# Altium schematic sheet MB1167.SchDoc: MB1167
size A3; DocumentNumber: MB1167; Revision: B.1; SheetNumber: 1; SheetTotal: 17; Project: STM327x6G-EVAL
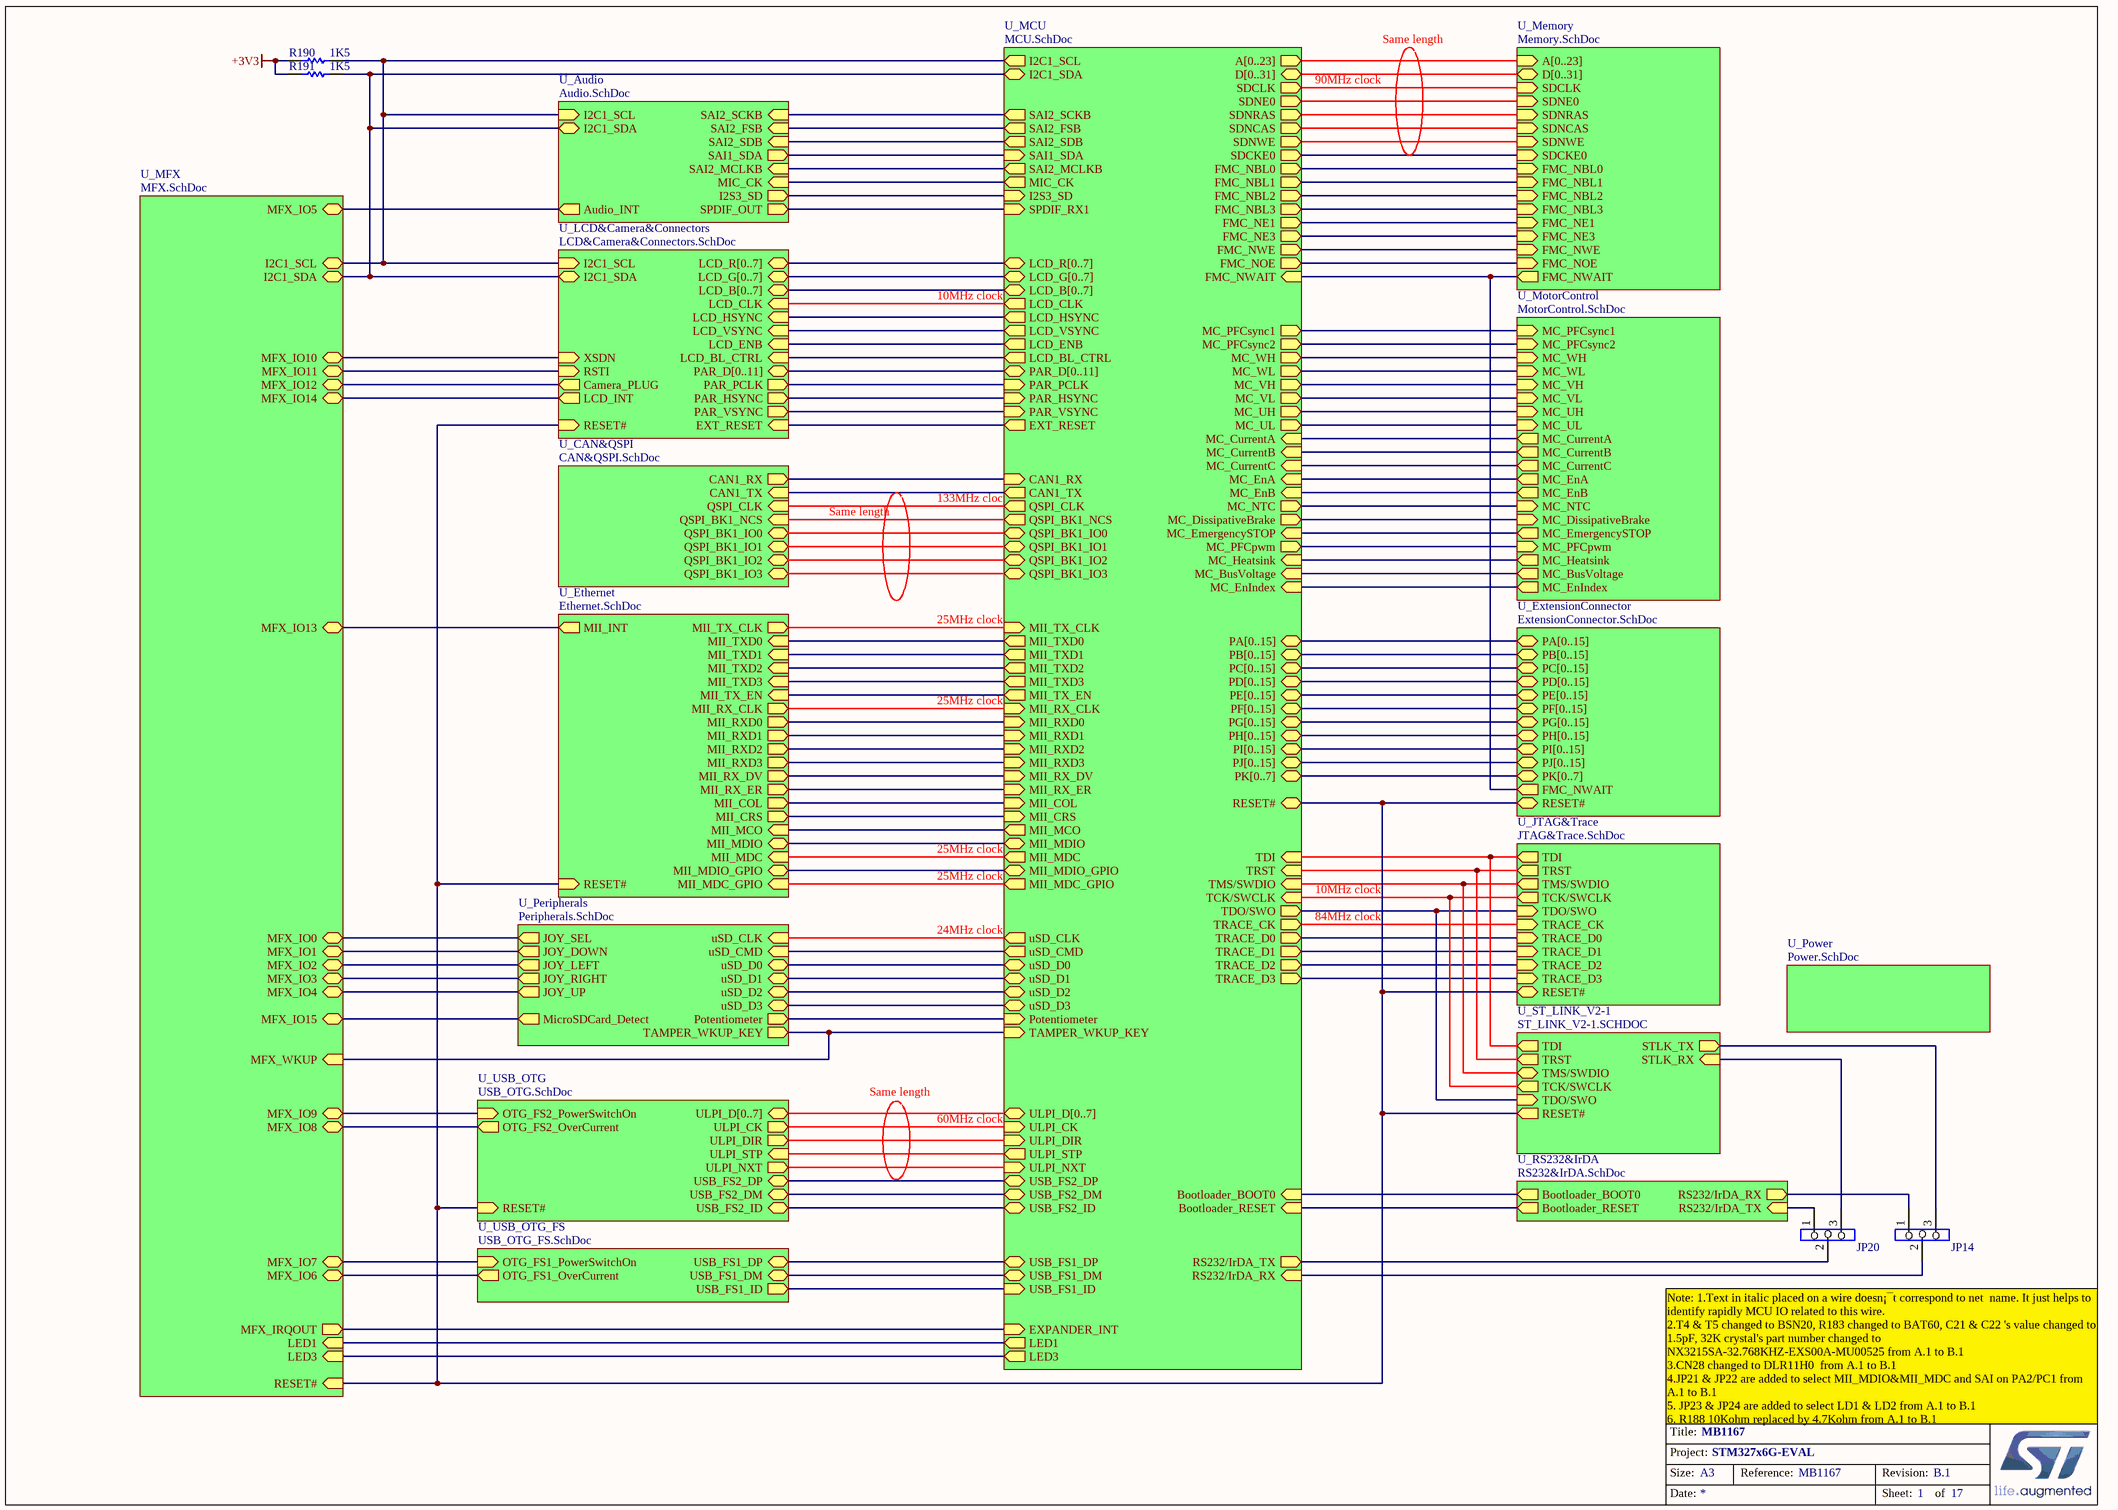
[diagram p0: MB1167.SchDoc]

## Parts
JP14  (no value)  [SIP3]
JP20  (no value)  [SIP3]
R190  1K5  [0603R]
R191  1K5  [0603R]

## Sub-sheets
U_Audio = Audio.SchDoc: SAI2_SCKB (in), SAI2_FSB (in), SAI2_SDB (in), SAI1_SDA (out), Audio_INT (out), I2C1_SDA (bidir), I2C1_SCL (in), SAI2_MCLKB (in), MIC_CK (in), I2S3_SD (out), SPDIF_OUT (out)
U_CAN&QSPI = CAN&QSPI.SchDoc: CAN1_TX (in), CAN1_RX (out), QSPI_BK1_IO0 (bidir), QSPI_BK1_IO3 (bidir), QSPI_BK1_IO2 (bidir), QSPI_BK1_IO1 (bidir), QSPI_CLK (in), QSPI_BK1_NCS (in)
U_Ethernet = Ethernet.SchDoc: MII_TXD0 (in), MII_TX_EN (in), MII_TX_CLK (out), MII_RXD0 (out), MII_RX_ER (out), MII_RX_DV (out), MII_RX_CLK (out), MII_COL (out), MII_CRS (out), MII_MDC (in), MII_MDIO (bidir), RESET# (in), MII_TXD1 (in), MII_TXD2 (in), MII_TXD3 (in), MII_RXD1 (out), MII_RXD2 (out), MII_RXD3 (out), MII_INT (out), MII_MCO (in), MII_MDIO_GPIO (bidir), MII_MDC_GPIO (in)
U_ExtensionConnector = ExtensionConnector.SchDoc: PA[0..15] (bidir), PB[0..15] (bidir), PC[0..15] (bidir), PD[0..15] (bidir), PE[0..15] (bidir), PF[0..15] (bidir), PG[0..15] (bidir), PH[0..15] (bidir), PI[0..15] (bidir), PJ[0..15] (bidir), PK[0..7] (bidir), RESET# (bidir), FMC_NWAIT (out)
U_JTAG&Trace = JTAG&Trace.SchDoc: TDI (out), RESET# (bidir), TRACE_D3 (in), TRACE_D2 (in), TRACE_D1 (in), TRACE_D0 (in), TRACE_CK (in), TRST (out), TMS/SWDIO (out), TCK/SWCLK (out), TDO/SWO (in)
U_LCD&Camera&Connectors = LCD&Camera&Connectors.SchDoc: LCD_R[0..7] (bidir), LCD_HSYNC (in), LCD_VSYNC (in), LCD_CLK (in), LCD_ENB (in), LCD_BL_CTRL (in), I2C1_SDA (bidir), I2C1_SCL (in), LCD_B[0..7] (bidir), LCD_G[0..7] (bidir), RSTI (in), XSDN (in), PAR_HSYNC (out), PAR_PCLK (out), PAR_VSYNC (out), PAR_D[0..11] (bidir), EXT_RESET (in), LCD_INT (out), Camera_PLUG (out), RESET# (in)
U_MCU = MCU.SchDoc: PA[0..15] (bidir), PB[0..15] (bidir), PC[0..15] (bidir), PD[0..15] (bidir), PE[0..15] (bidir), PF[0..15] (bidir), PG[0..15] (bidir), PH[0..15] (bidir), PI[0..15] (bidir), MC_EnA (in), MII_RX_CLK (in), MC_EnB (in), MII_MDIO (bidir), MC_EnIndex (in), ULPI_CK (in), MC_EmergencySTOP (in), MII_RX_DV (in), MC_UL (out), LCD_BL_CTRL (out), MC_PFCsync1 (out), RS232/IrDA_TX (out), RS232/IrDA_RX (in), USB_FS1_ID (in), CAN1_RX (in), USB_FS1_DM (bidir), MC_PFCpwm (out), CAN1_TX (out), USB_FS1_DP (bidir), MC_PFCsync2 (out), TMS/SWDIO (in), TCK/SWCLK (in), TDI (in), MC_VL (out), MC_WL (out), TDO/SWO (out), MIC_CK (out), TRST (in), I2C1_SCL (out), MII_TXD3 (out), MC_DissipativeBrake (out), I2C1_SDA (bidir), USB_FS2_ID (bidir), USB_FS2_DM (bidir), USB_FS2_DP (bidir), ULPI_STP (out), MII_MDC (out), MC_CurrentA (in), MII_TXD2 (out), MC_CurrentB (in), MII_TX_CLK (in), MC_CurrentC (in), MII_RXD0 (in), MC_BusVoltage (in), MII_RXD1 (in), MC_Heatsink (in), MC_UH (out), MC_VH (out), uSD_D0 (bidir), MC_WH (out), uSD_D1 (bidir), uSD_D2 (bidir), EXT_RESET (out), uSD_D3 (bidir), uSD_CLK (out), TAMPER_WKUP_KEY (in), MII_CRS (in), LCD_ENB (out), uSD_CMD (out), FMC_NOE (out), FMC_NWE (out), FMC_NWAIT (in), I2S3_SD (in), FMC_NE1 (out), FMC_NBL3 (out), FMC_NBL2 (out), EXPANDER_INT (in), MII_RX_ER (in), ULPI_DIR (in), LCD_HSYNC (out), LCD_VSYNC (out), LCD_CLK (out), FMC_NBL0 (out), FMC_NBL1 (out), TRACE_CK (out), TRACE_D0 (out), TRACE_D2 (out), TRACE_D1 (out), SAI1_SDA (in), TRACE_D3 (out), SAI2_SDB (out), SAI2_SCKB (out), SAI2_FSB (out), SAI2_MCLKB (out), Potentiometer (in), SDNRAS (out), MII_MDIO_GPIO (bidir), MII_MDC_GPIO (out), SDCLK (out), FMC_NE3 (out), SPDIF_RX1 (in), MII_TX_EN (out), MC_NTC (out), MII_TXD0 (out), MII_TXD1 (out), SDNCAS (out), SDCKE0 (out), SDNE0 (out), MII_COL (in), ULPI_NXT (in), SDNWE (out), MII_RXD2 (in), MII_RXD3 (in), LCD_G[0..7] (bidir), LCD_B[0..7] (bidir), D[0..31] (bidir), A[0..23] (out), ULPI_D[0..7] (bidir), RESET# (bidir), PJ[0..15] (bidir), PK[0..7] (bidir), PAR_VSYNC (in), PAR_D[0..11] (bidir), PAR_PCLK (in), PAR_HSYNC (in), MII_MCO (out), LCD_R[0..7] (bidir), Bootloader_BOOT0 (in), QSPI_CLK (out), QSPI_BK1_NCS (out), QSPI_BK1_IO3 (bidir), QSPI_BK1_IO2 (bidir), QSPI_BK1_IO1 (bidir), QSPI_BK1_IO0 (bidir), Bootloader_RESET (in), LED1 (out), LED3 (out)
U_Memory = Memory.SchDoc: FMC_NE1 (in), FMC_NWE (in), FMC_NOE (in), FMC_NWAIT (out), FMC_NBL0 (in), FMC_NBL1 (in), D[0..31] (bidir), A[0..23] (in), SDNCAS (in), SDNWE (in), SDNRAS (in), SDNE0 (in), SDCKE0 (in), SDCLK (in), FMC_NBL3 (in), FMC_NBL2 (in), FMC_NE3 (in)
U_MFX = MFX.SchDoc: I2C1_SDA (bidir), I2C1_SCL (bidir), MFX_IO5 (bidir), MFX_IO6 (bidir), MFX_IO7 (bidir), MFX_IO8 (bidir), MFX_IO9 (bidir), MFX_IO10 (bidir), MFX_IO11 (bidir), MFX_IO12 (bidir), MFX_IO13 (bidir), MFX_IO14 (bidir), MFX_IO15 (bidir), MFX_IO0 (bidir), MFX_IO1 (bidir), MFX_IO2 (bidir), MFX_IO3 (bidir), MFX_IO4 (bidir), MFX_IRQOUT (out), MFX_WKUP (in), RESET# (in), LED1 (in), LED3 (in)
U_MotorControl = MotorControl.SchDoc: MC_EmergencySTOP (out), MC_CurrentA (out), MC_CurrentB (out), MC_CurrentC (out), MC_PFCsync1 (in), MC_PFCsync2 (in), MC_WL (in), MC_VH (in), MC_VL (in), MC_UH (in), MC_UL (in), MC_WH (in), MC_NTC (in), MC_DissipativeBrake (in), MC_PFCpwm (in), MC_EnA (out), MC_EnB (out), MC_Heatsink (out), MC_BusVoltage (out), MC_EnIndex (out)
U_Peripherals = Peripherals.SchDoc: JOY_SEL (out), JOY_DOWN (out), JOY_LEFT (out), JOY_RIGHT (out), JOY_UP (out), Potentiometer (out), TAMPER_WKUP_KEY (out), uSD_CLK (in), uSD_CMD (in), uSD_D0 (bidir), uSD_D1 (bidir), uSD_D2 (bidir), uSD_D3 (bidir), MicroSDCard_Detect (out)
U_Power = Power.SchDoc: no entries
U_RS232&IrDA = RS232&IrDA.SchDoc: RS232/IrDA_TX (in), RS232/IrDA_RX (out), Bootloader_BOOT0 (out), Bootloader_RESET (out)
U_ST_LINK_V2-1 = ST_LINK_V2-1.SCHDOC: STLK_RX (in), STLK_TX (out), TDI (out), TRST (out), TMS/SWDIO (bidir), TCK/SWCLK (out), TDO/SWO (in), RESET# (out)
U_USB_OTG = USB_OTG.SchDoc: ULPI_D[0..7] (bidir), ULPI_CK (out), ULPI_DIR (out), ULPI_NXT (out), ULPI_STP (in), RESET# (in), USB_FS2_DM (bidir), USB_FS2_DP (bidir), OTG_FS2_PowerSwitchOn (in), OTG_FS2_OverCurrent (out), USB_FS2_ID (bidir)
U_USB_OTG_FS = USB_OTG_FS.SchDoc: OTG_FS1_PowerSwitchOn (in), OTG_FS1_OverCurrent (out), USB_FS1_DM (bidir), USB_FS1_DP (bidir), USB_FS1_ID (out)

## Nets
+3V3: R190.1 R191.1
NetJP14_1: JP14.1 ; sheet U_RS232&IrDA/RS232/IrDA_RX
NetJP14_2: JP14.2 ; sheet U_MCU/RS232/IrDA_RX
NetJP14_3: JP14.3 ; sheet U_ST_LINK_V2-1/STLK_TX
NetJP20_1: JP20.1 ; sheet U_RS232&IrDA/RS232/IrDA_TX
NetJP20_2: JP20.2 ; sheet U_MCU/RS232/IrDA_TX
NetJP20_3: JP20.3 ; sheet U_ST_LINK_V2-1/STLK_RX
NetR190_2: R190.2 ; sheet U_Audio/I2C1_SCL, sheet U_LCD&Camera&Connectors/I2C1_SCL, sheet U_MFX/I2C1_SCL, sheet U_MCU/I2C1_SCL
NetR191_2: R191.2 ; sheet U_Audio/I2C1_SDA, sheet U_LCD&Camera&Connectors/I2C1_SDA, sheet U_MFX/I2C1_SDA, sheet U_MCU/I2C1_SDA
(unnamed): sheet U_Audio/SAI2_SCKB, sheet U_MCU/SAI2_SCKB
(unnamed): sheet U_Audio/SAI2_FSB, sheet U_MCU/SAI2_FSB  [a separate net that carries the same name]
(unnamed): sheet U_Audio/SAI2_SDB, sheet U_MCU/SAI2_SDB  [a separate net that carries the same name]
(unnamed): sheet U_Audio/SAI1_SDA, sheet U_MCU/SAI1_SDA  [a separate net that carries the same name]
(unnamed): sheet U_Audio/Audio_INT, sheet U_MFX/MFX_IO5  [a separate net that carries the same name]
(unnamed): sheet U_Audio/SAI2_MCLKB, sheet U_MCU/SAI2_MCLKB  [a separate net that carries the same name]
(unnamed): sheet U_Audio/MIC_CK, sheet U_MCU/MIC_CK  [a separate net that carries the same name]
(unnamed): sheet U_Audio/I2S3_SD, sheet U_MCU/I2S3_SD  [a separate net that carries the same name]
(unnamed): sheet U_Audio/SPDIF_OUT, sheet U_MCU/SPDIF_RX1  [a separate net that carries the same name]
(unnamed): sheet U_CAN&QSPI/CAN1_TX, sheet U_MCU/CAN1_TX  [a separate net that carries the same name]
(unnamed): sheet U_CAN&QSPI/CAN1_RX, sheet U_MCU/CAN1_RX  [a separate net that carries the same name]
(unnamed): sheet U_CAN&QSPI/QSPI_BK1_IO0, sheet U_MCU/QSPI_BK1_IO0  [a separate net that carries the same name]
(unnamed): sheet U_CAN&QSPI/QSPI_BK1_IO3, sheet U_MCU/QSPI_BK1_IO3  [a separate net that carries the same name]
(unnamed): sheet U_CAN&QSPI/QSPI_BK1_IO2, sheet U_MCU/QSPI_BK1_IO2  [a separate net that carries the same name]
(unnamed): sheet U_CAN&QSPI/QSPI_BK1_IO1, sheet U_MCU/QSPI_BK1_IO1  [a separate net that carries the same name]
(unnamed): sheet U_CAN&QSPI/QSPI_CLK, sheet U_MCU/QSPI_CLK  [a separate net that carries the same name]
(unnamed): sheet U_CAN&QSPI/QSPI_BK1_NCS, sheet U_MCU/QSPI_BK1_NCS  [a separate net that carries the same name]
(unnamed): sheet U_Ethernet/MII_TXD0, sheet U_MCU/MII_TXD0  [a separate net that carries the same name]
(unnamed): sheet U_Ethernet/MII_TX_EN, sheet U_MCU/MII_TX_EN  [a separate net that carries the same name]
(unnamed): sheet U_Ethernet/MII_TX_CLK, sheet U_MCU/MII_TX_CLK  [a separate net that carries the same name]
(unnamed): sheet U_Ethernet/MII_RXD0, sheet U_MCU/MII_RXD0  [a separate net that carries the same name]
(unnamed): sheet U_Ethernet/MII_RX_ER, sheet U_MCU/MII_RX_ER  [a separate net that carries the same name]
(unnamed): sheet U_Ethernet/MII_RX_DV, sheet U_MCU/MII_RX_DV  [a separate net that carries the same name]
(unnamed): sheet U_Ethernet/MII_RX_CLK, sheet U_MCU/MII_RX_CLK  [a separate net that carries the same name]
(unnamed): sheet U_Ethernet/MII_COL, sheet U_MCU/MII_COL  [a separate net that carries the same name]
(unnamed): sheet U_Ethernet/MII_CRS, sheet U_MCU/MII_CRS  [a separate net that carries the same name]
(unnamed): sheet U_Ethernet/MII_MDC, sheet U_MCU/MII_MDC  [a separate net that carries the same name]
(unnamed): sheet U_Ethernet/MII_MDIO, sheet U_MCU/MII_MDIO  [a separate net that carries the same name]
(unnamed): sheet U_Ethernet/RESET#, sheet U_ExtensionConnector/RESET#, sheet U_JTAG&Trace/RESET#, sheet U_ST_LINK_V2-1/RESET#, sheet U_USB_OTG/RESET#, sheet U_LCD&Camera&Connectors/RESET#, sheet U_MFX/RESET#, sheet U_MCU/RESET#  [a separate net that carries the same name]
(unnamed): sheet U_Ethernet/MII_TXD1, sheet U_MCU/MII_TXD1  [a separate net that carries the same name]
(unnamed): sheet U_Ethernet/MII_TXD2, sheet U_MCU/MII_TXD2  [a separate net that carries the same name]
(unnamed): sheet U_Ethernet/MII_TXD3, sheet U_MCU/MII_TXD3  [a separate net that carries the same name]
(unnamed): sheet U_Ethernet/MII_RXD1, sheet U_MCU/MII_RXD1  [a separate net that carries the same name]
(unnamed): sheet U_Ethernet/MII_RXD2, sheet U_MCU/MII_RXD2  [a separate net that carries the same name]
(unnamed): sheet U_Ethernet/MII_RXD3, sheet U_MCU/MII_RXD3  [a separate net that carries the same name]
(unnamed): sheet U_Ethernet/MII_INT, sheet U_MFX/MFX_IO13  [a separate net that carries the same name]
(unnamed): sheet U_Ethernet/MII_MCO, sheet U_MCU/MII_MCO  [a separate net that carries the same name]
(unnamed): sheet U_Ethernet/MII_MDIO_GPIO, sheet U_MCU/MII_MDIO_GPIO  [a separate net that carries the same name]
(unnamed): sheet U_Ethernet/MII_MDC_GPIO, sheet U_MCU/MII_MDC_GPIO  [a separate net that carries the same name]
(unnamed): sheet U_ExtensionConnector/FMC_NWAIT, sheet U_Memory/FMC_NWAIT, sheet U_MCU/FMC_NWAIT  [a separate net that carries the same name]
(unnamed): sheet U_JTAG&Trace/TDI, sheet U_ST_LINK_V2-1/TDI, sheet U_MCU/TDI  [a separate net that carries the same name]
(unnamed): sheet U_JTAG&Trace/TRACE_D3, sheet U_MCU/TRACE_D3  [a separate net that carries the same name]
(unnamed): sheet U_JTAG&Trace/TRACE_D2, sheet U_MCU/TRACE_D2  [a separate net that carries the same name]
(unnamed): sheet U_JTAG&Trace/TRACE_D1, sheet U_MCU/TRACE_D1  [a separate net that carries the same name]
(unnamed): sheet U_JTAG&Trace/TRACE_D0, sheet U_MCU/TRACE_D0  [a separate net that carries the same name]
(unnamed): sheet U_JTAG&Trace/TRACE_CK, sheet U_MCU/TRACE_CK  [a separate net that carries the same name]
(unnamed): sheet U_JTAG&Trace/TRST, sheet U_ST_LINK_V2-1/TRST, sheet U_MCU/TRST  [a separate net that carries the same name]
(unnamed): sheet U_JTAG&Trace/TMS/SWDIO, sheet U_ST_LINK_V2-1/TMS/SWDIO, sheet U_MCU/TMS/SWDIO  [a separate net that carries the same name]
(unnamed): sheet U_JTAG&Trace/TCK/SWCLK, sheet U_ST_LINK_V2-1/TCK/SWCLK, sheet U_MCU/TCK/SWCLK  [a separate net that carries the same name]
(unnamed): sheet U_JTAG&Trace/TDO/SWO, sheet U_ST_LINK_V2-1/TDO/SWO, sheet U_MCU/TDO/SWO  [a separate net that carries the same name]
(unnamed): sheet U_Memory/FMC_NE1, sheet U_MCU/FMC_NE1  [a separate net that carries the same name]
(unnamed): sheet U_Memory/FMC_NWE, sheet U_MCU/FMC_NWE  [a separate net that carries the same name]
(unnamed): sheet U_Memory/FMC_NOE, sheet U_MCU/FMC_NOE  [a separate net that carries the same name]
(unnamed): sheet U_Memory/FMC_NBL0, sheet U_MCU/FMC_NBL0  [a separate net that carries the same name]
(unnamed): sheet U_Memory/FMC_NBL1, sheet U_MCU/FMC_NBL1  [a separate net that carries the same name]
(unnamed): sheet U_Memory/SDNCAS, sheet U_MCU/SDNCAS  [a separate net that carries the same name]
(unnamed): sheet U_Memory/SDNWE, sheet U_MCU/SDNWE  [a separate net that carries the same name]
(unnamed): sheet U_Memory/SDNRAS, sheet U_MCU/SDNRAS  [a separate net that carries the same name]
(unnamed): sheet U_Memory/SDNE0, sheet U_MCU/SDNE0  [a separate net that carries the same name]
(unnamed): sheet U_Memory/SDCKE0, sheet U_MCU/SDCKE0  [a separate net that carries the same name]
(unnamed): sheet U_Memory/SDCLK, sheet U_MCU/SDCLK  [a separate net that carries the same name]
(unnamed): sheet U_Memory/FMC_NBL3, sheet U_MCU/FMC_NBL3  [a separate net that carries the same name]
(unnamed): sheet U_Memory/FMC_NBL2, sheet U_MCU/FMC_NBL2  [a separate net that carries the same name]
(unnamed): sheet U_Memory/FMC_NE3, sheet U_MCU/FMC_NE3  [a separate net that carries the same name]
(unnamed): sheet U_MotorControl/MC_EmergencySTOP, sheet U_MCU/MC_EmergencySTOP  [a separate net that carries the same name]
(unnamed): sheet U_MotorControl/MC_CurrentA, sheet U_MCU/MC_CurrentA  [a separate net that carries the same name]
(unnamed): sheet U_MotorControl/MC_CurrentB, sheet U_MCU/MC_CurrentB  [a separate net that carries the same name]
(unnamed): sheet U_MotorControl/MC_CurrentC, sheet U_MCU/MC_CurrentC  [a separate net that carries the same name]
(unnamed): sheet U_MotorControl/MC_PFCsync1, sheet U_MCU/MC_PFCsync1  [a separate net that carries the same name]
(unnamed): sheet U_MotorControl/MC_PFCsync2, sheet U_MCU/MC_PFCsync2  [a separate net that carries the same name]
(unnamed): sheet U_MotorControl/MC_WL, sheet U_MCU/MC_WL  [a separate net that carries the same name]
(unnamed): sheet U_MotorControl/MC_VH, sheet U_MCU/MC_VH  [a separate net that carries the same name]
(unnamed): sheet U_MotorControl/MC_VL, sheet U_MCU/MC_VL  [a separate net that carries the same name]
(unnamed): sheet U_MotorControl/MC_UH, sheet U_MCU/MC_UH  [a separate net that carries the same name]
(unnamed): sheet U_MotorControl/MC_UL, sheet U_MCU/MC_UL  [a separate net that carries the same name]
(unnamed): sheet U_MotorControl/MC_WH, sheet U_MCU/MC_WH  [a separate net that carries the same name]
(unnamed): sheet U_MotorControl/MC_NTC, sheet U_MCU/MC_NTC  [a separate net that carries the same name]
(unnamed): sheet U_MotorControl/MC_DissipativeBrake, sheet U_MCU/MC_DissipativeBrake  [a separate net that carries the same name]
(unnamed): sheet U_MotorControl/MC_PFCpwm, sheet U_MCU/MC_PFCpwm  [a separate net that carries the same name]
(unnamed): sheet U_MotorControl/MC_EnA, sheet U_MCU/MC_EnA  [a separate net that carries the same name]
(unnamed): sheet U_MotorControl/MC_EnB, sheet U_MCU/MC_EnB  [a separate net that carries the same name]
(unnamed): sheet U_MotorControl/MC_Heatsink, sheet U_MCU/MC_Heatsink  [a separate net that carries the same name]
(unnamed): sheet U_MotorControl/MC_BusVoltage, sheet U_MCU/MC_BusVoltage  [a separate net that carries the same name]
(unnamed): sheet U_MotorControl/MC_EnIndex, sheet U_MCU/MC_EnIndex  [a separate net that carries the same name]
(unnamed): sheet U_Peripherals/JOY_SEL, sheet U_MFX/MFX_IO0  [a separate net that carries the same name]
(unnamed): sheet U_Peripherals/JOY_DOWN, sheet U_MFX/MFX_IO1  [a separate net that carries the same name]
(unnamed): sheet U_Peripherals/JOY_LEFT, sheet U_MFX/MFX_IO2  [a separate net that carries the same name]
(unnamed): sheet U_Peripherals/JOY_RIGHT, sheet U_MFX/MFX_IO3  [a separate net that carries the same name]
(unnamed): sheet U_Peripherals/JOY_UP, sheet U_MFX/MFX_IO4  [a separate net that carries the same name]
(unnamed): sheet U_Peripherals/Potentiometer, sheet U_MCU/Potentiometer  [a separate net that carries the same name]
(unnamed): sheet U_Peripherals/TAMPER_WKUP_KEY, sheet U_MFX/MFX_WKUP, sheet U_MCU/TAMPER_WKUP_KEY  [a separate net that carries the same name]
(unnamed): sheet U_Peripherals/uSD_CLK, sheet U_MCU/uSD_CLK  [a separate net that carries the same name]
(unnamed): sheet U_Peripherals/uSD_CMD, sheet U_MCU/uSD_CMD  [a separate net that carries the same name]
(unnamed): sheet U_Peripherals/uSD_D0, sheet U_MCU/uSD_D0  [a separate net that carries the same name]
(unnamed): sheet U_Peripherals/uSD_D1, sheet U_MCU/uSD_D1  [a separate net that carries the same name]
(unnamed): sheet U_Peripherals/uSD_D2, sheet U_MCU/uSD_D2  [a separate net that carries the same name]
(unnamed): sheet U_Peripherals/uSD_D3, sheet U_MCU/uSD_D3  [a separate net that carries the same name]
(unnamed): sheet U_Peripherals/MicroSDCard_Detect, sheet U_MFX/MFX_IO15  [a separate net that carries the same name]
(unnamed): sheet U_USB_OTG/ULPI_CK, sheet U_MCU/ULPI_CK  [a separate net that carries the same name]
(unnamed): sheet U_USB_OTG/ULPI_DIR, sheet U_MCU/ULPI_DIR  [a separate net that carries the same name]
(unnamed): sheet U_USB_OTG/ULPI_NXT, sheet U_MCU/ULPI_NXT  [a separate net that carries the same name]
(unnamed): sheet U_USB_OTG/ULPI_STP, sheet U_MCU/ULPI_STP  [a separate net that carries the same name]
(unnamed): sheet U_USB_OTG/USB_FS2_DM, sheet U_MCU/USB_FS2_DM  [a separate net that carries the same name]
(unnamed): sheet U_USB_OTG/USB_FS2_DP, sheet U_MCU/USB_FS2_DP  [a separate net that carries the same name]
(unnamed): sheet U_USB_OTG/OTG_FS2_PowerSwitchOn, sheet U_MFX/MFX_IO9  [a separate net that carries the same name]
(unnamed): sheet U_USB_OTG/OTG_FS2_OverCurrent, sheet U_MFX/MFX_IO8  [a separate net that carries the same name]
(unnamed): sheet U_USB_OTG/USB_FS2_ID, sheet U_MCU/USB_FS2_ID  [a separate net that carries the same name]
(unnamed): sheet U_USB_OTG_FS/OTG_FS1_PowerSwitchOn, sheet U_MFX/MFX_IO7  [a separate net that carries the same name]
(unnamed): sheet U_USB_OTG_FS/OTG_FS1_OverCurrent, sheet U_MFX/MFX_IO6  [a separate net that carries the same name]
(unnamed): sheet U_USB_OTG_FS/USB_FS1_DM, sheet U_MCU/USB_FS1_DM  [a separate net that carries the same name]
(unnamed): sheet U_USB_OTG_FS/USB_FS1_DP, sheet U_MCU/USB_FS1_DP  [a separate net that carries the same name]
(unnamed): sheet U_USB_OTG_FS/USB_FS1_ID, sheet U_MCU/USB_FS1_ID  [a separate net that carries the same name]
(unnamed): sheet U_RS232&IrDA/Bootloader_BOOT0, sheet U_MCU/Bootloader_BOOT0  [a separate net that carries the same name]
(unnamed): sheet U_RS232&IrDA/Bootloader_RESET, sheet U_MCU/Bootloader_RESET  [a separate net that carries the same name]
(unnamed): sheet U_LCD&Camera&Connectors/LCD_HSYNC, sheet U_MCU/LCD_HSYNC  [a separate net that carries the same name]
(unnamed): sheet U_LCD&Camera&Connectors/LCD_VSYNC, sheet U_MCU/LCD_VSYNC  [a separate net that carries the same name]
(unnamed): sheet U_LCD&Camera&Connectors/LCD_CLK, sheet U_MCU/LCD_CLK  [a separate net that carries the same name]
(unnamed): sheet U_LCD&Camera&Connectors/LCD_ENB, sheet U_MCU/LCD_ENB  [a separate net that carries the same name]
(unnamed): sheet U_LCD&Camera&Connectors/LCD_BL_CTRL, sheet U_MCU/LCD_BL_CTRL  [a separate net that carries the same name]
(unnamed): sheet U_LCD&Camera&Connectors/RSTI, sheet U_MFX/MFX_IO11  [a separate net that carries the same name]
(unnamed): sheet U_LCD&Camera&Connectors/XSDN, sheet U_MFX/MFX_IO10  [a separate net that carries the same name]
(unnamed): sheet U_LCD&Camera&Connectors/PAR_HSYNC, sheet U_MCU/PAR_HSYNC  [a separate net that carries the same name]
(unnamed): sheet U_LCD&Camera&Connectors/PAR_PCLK, sheet U_MCU/PAR_PCLK  [a separate net that carries the same name]
(unnamed): sheet U_LCD&Camera&Connectors/PAR_VSYNC, sheet U_MCU/PAR_VSYNC  [a separate net that carries the same name]
(unnamed): sheet U_LCD&Camera&Connectors/EXT_RESET, sheet U_MCU/EXT_RESET  [a separate net that carries the same name]
(unnamed): sheet U_LCD&Camera&Connectors/LCD_INT, sheet U_MFX/MFX_IO14  [a separate net that carries the same name]
(unnamed): sheet U_LCD&Camera&Connectors/Camera_PLUG, sheet U_MFX/MFX_IO12  [a separate net that carries the same name]
(unnamed): sheet U_MFX/MFX_IRQOUT, sheet U_MCU/EXPANDER_INT  [a separate net that carries the same name]
(unnamed): sheet U_MFX/LED1, sheet U_MCU/LED1  [a separate net that carries the same name]
(unnamed): sheet U_MFX/LED3, sheet U_MCU/LED3  [a separate net that carries the same name]

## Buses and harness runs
bus sheet U_ExtensionConnector/PA[0..15] = sheet U_MCU/PA[0..15]
bus sheet U_ExtensionConnector/PB[0..15] = sheet U_MCU/PB[0..15]
bus sheet U_ExtensionConnector/PC[0..15] = sheet U_MCU/PC[0..15]
bus sheet U_ExtensionConnector/PD[0..15] = sheet U_MCU/PD[0..15]
bus sheet U_ExtensionConnector/PE[0..15] = sheet U_MCU/PE[0..15]
bus sheet U_ExtensionConnector/PF[0..15] = sheet U_MCU/PF[0..15]
bus sheet U_ExtensionConnector/PG[0..15] = sheet U_MCU/PG[0..15]
bus sheet U_ExtensionConnector/PH[0..15] = sheet U_MCU/PH[0..15]
bus sheet U_ExtensionConnector/PI[0..15] = sheet U_MCU/PI[0..15]
bus sheet U_ExtensionConnector/PJ[0..15] = sheet U_MCU/PJ[0..15]
bus sheet U_ExtensionConnector/PK[0..7] = sheet U_MCU/PK[0..7]
bus sheet U_LCD&Camera&Connectors/LCD_B[0..7] = sheet U_MCU/LCD_B[0..7]
bus sheet U_LCD&Camera&Connectors/LCD_G[0..7] = sheet U_MCU/LCD_G[0..7]
bus sheet U_LCD&Camera&Connectors/LCD_R[0..7] = sheet U_MCU/LCD_R[0..7]
bus sheet U_LCD&Camera&Connectors/PAR_D[0..11] = sheet U_MCU/PAR_D[0..11]
bus sheet U_MCU/A[0..23] = sheet U_Memory/A[0..23]
bus sheet U_MCU/D[0..31] = sheet U_Memory/D[0..31]
bus sheet U_MCU/ULPI_D[0..7] = sheet U_USB_OTG/ULPI_D[0..7]

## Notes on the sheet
- Same length
- 90MHz clock
- 10MHz clock
- 133MHz clock
- 25MHz clock
- 84MHz clock
- 24MHz clock
- 60MHz clock
- Note: 1.Text in italic placed on a wire doesn¡¯t correspond to net  name. It just helps to identify rapidly MCU IO related to this wire.
  2.T4 & T5 changed to BSN20, R183 changed to BAT60, C21 & C22 's value changed to 1.5pF, 32K crystal's part number changed to NX3215SA-32.768KHZ-EXS00A-MU00525 from A.1 to B.1
  3.CN28 changed to DLR11H0  from A.1 to B.1
  4.JP21 & JP22 are added to select MII_MDIO&MII_MDC and SAI on PA2/PC1 from A.1 to B.1
  5. JP23 & JP24 are added to select LD1 & LD2 from A.1 to B.1
  6. R188 10Kohm replaced by 4.7Kohm from A.1 to B.1

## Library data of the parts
JP14 JP20 = Jumper3
R190 R191 = Res1: Resistor; Value: 1K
